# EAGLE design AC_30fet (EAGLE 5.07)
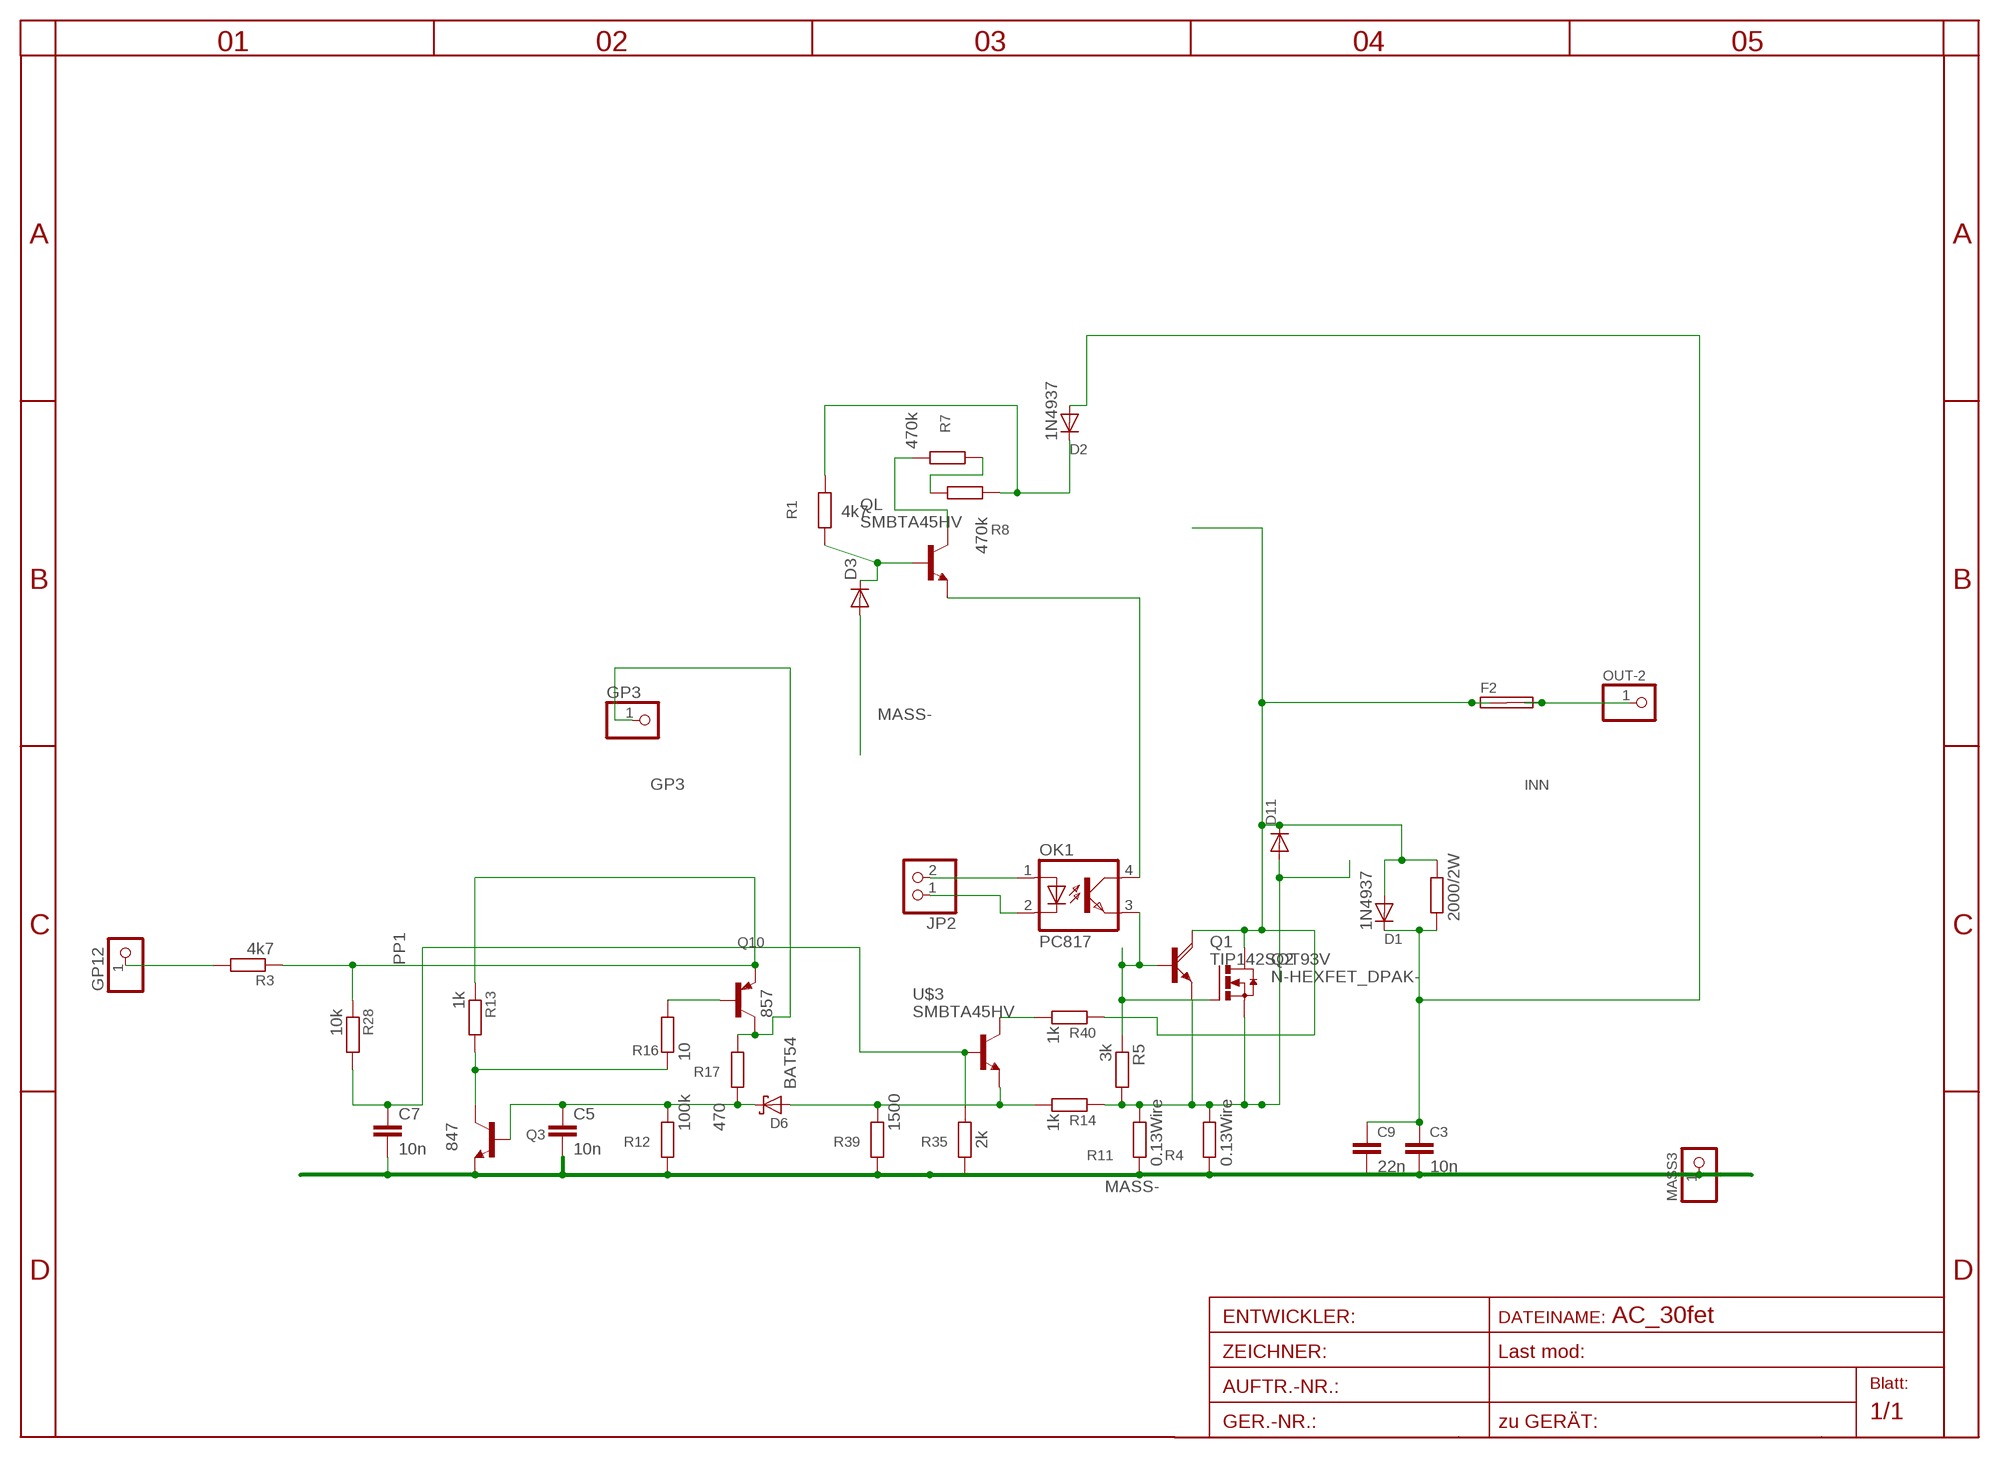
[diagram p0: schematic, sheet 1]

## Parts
C3  10n  C-EU025_050-050X075  [C025_050-050X075]
C5  10n  C-EUC0805  [C0805]
C7  10n  C-EUC0805  [C0805]
C9  22n  C-EU150-054X183  [C150-054X183]
D1  1N4937  1N4004DO41-10  [DO41-10]
D2  1N4937  1N400420  [DO41-20]
D3  DIODE-MINIMELF  [MINIMELF]
D6  BAT54  [SOT23]
D11  DIODE-SMC  [SMC]
F2  SHK20L7MM5  [7MM5]
GP3  PINHD-1X11X0.4  [1X01]
GP12  PINHD-1X11X0.4  [1X01]
JP2  PINHD-1X2STR  [1X02]
MASS3  PINHD-1X13MM2  [1X3MM2]
OK1  PC817  [DIL04]
OUT-2  PINHD-1X13MM2  [1X3MM2]
Q1  TIP142SOT93V  [SOT93V]
Q2  N-HEXFET_DPAK-  [TO252]
Q3  847  BC846ALT1SMD  [SOT23]
Q10  857  BC857ALT1SMD  [SOT23-BEC]
QL  SMBTA45HV  [SOT23HV]
R1  4k7  R-EU_R1206  [R1206]
R3  4k7  R-EU_R0805  [R0805]
R4  0.13Wire  R-EU_0204/5  [0204/5]
R5  3k  R-EU_0207/15  [0207/15]
R7  470k  R-EU_R1206  [R1206]
R8  470k  R-EU_R1206  [R1206]
R11  0.13Wire  R-EU_0204/5  [0204/5]
R12  100k  R-EU_R0805  [R0805]
R13  1k  R-EU_R0805  [R0805]
R14  1k  R-EU_R0805  [R0805]
R16  10  R-EU_R0805  [R0805]
R17  470  R-EU_R0805  [R0805]
R27  2000/2W  R-EU_0207/10  [0207/10]
R28  10k  R-EU_R0805  [R0805]
R35  2k  R-EU_R0805  [R0805]
R39  1500  R-EU_R0805  [R0805]
R40  1k  R-EU_R1206  [R1206]
U$3  SMBTA45HV  [SOT23HV]

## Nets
BQL: D3.C QL.1(B) R1.2
D1: D1.A D11.C F2.1A F2.1B Q1.C Q2.3(D) R27.2 R40.2
DK1: C5.1 D6.3(C) Q3.1(B) R12.1 R17.2
FUSE: GP3.1 Q10.C R17.1
GP3: Q3.3(C) R13.2 R16.1
INN: F2.2A F2.2B OUT-2.1
MASS-: C3.3 C5.2 C7.2 C9.2 D3.A MASS3.1 Q3.2(E) R4.1 R11.1 R12.2 R35.2 R39.2
N$1: R7.1 R8.2
N$2: C3.1 C9.1 D1.C D2.A R27.1
N$3: JP2.1 OK1.2(C)
N$4: OK1.3(EMIT) Q1.B Q2.1(G) R5.1
N$6: D2.C R1.1 R8.1
N$7: JP2.2 OK1.1(A)
N$9: QL.3(C) R7.2
N$11: OK1.4(COL) QL.2(E)
N$12: GP12.1 R3.2
N$14: R40.1 U$3.3(C)
N$16: Q10.B R16.2
N$40: C7.1 R28.2 R35.1 U$3.1(B)
PP1: Q10.E R3.1 R13.1 R28.1
SRC1: D11.A Q1.E Q2.2(S) R4.2 R5.2 R11.2 R14.2
T1E: D6.1(A) R14.1 R39.1 U$3.2(E)

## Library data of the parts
C3 C9 = rcl-2:C-EU: CAPACITOR, European symbol
C5 C7 = rcl:C-EU: CAPACITOR, European symbol
D1 D2 = diode:1N4004: DIODE
D3 D11 = diode:DIODE-: DIODE
D6 = diode:BAT54: Schottky Diodes
F2 = fuse:SHK20L: FUSE HOLDER 5 x 20 mm, SH contact, SHH1 Schukat, E1073 Buerklin
GP3 GP12 MASS3 OUT-2 = pinhead:PINHD-1X1: PIN HEADER
JP2 = pinhead:PINHD-1X2: PIN HEADER
OK1 = optocoupler:PC817: SHARP OPTO COUPLER
Q1 = transistor-power:TIP142: NPN DARLINGTON TRANSISTOR
Q2 = transistor-power:N-HEXFET_?-*: HEXFET® Power MOSFET
Q3 = transistor-npn:BC846*: NPN Transistor
Q10 = transistor-pnp:BC857*: PNP Transistror
QL U$3 = transistor-npn:SMBTA45
R1 R3-R5 R7 R8 R11-R14 R16 R17 R27 R28 R35 R39 R40 = rcl-2:R-EU_: RESISTOR, European symbol

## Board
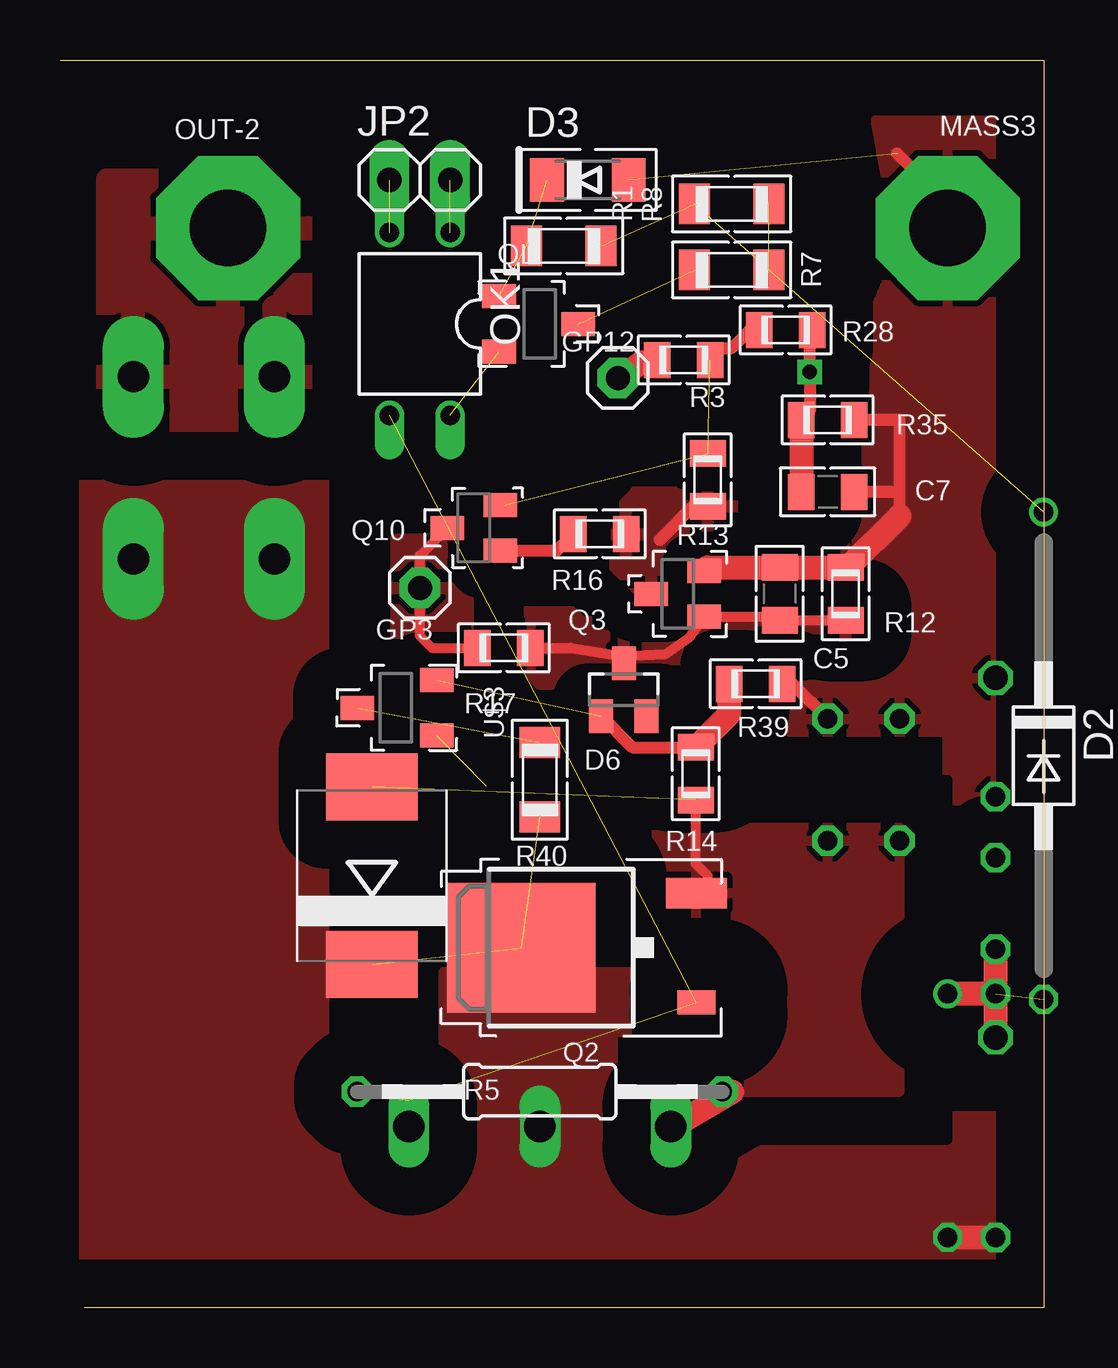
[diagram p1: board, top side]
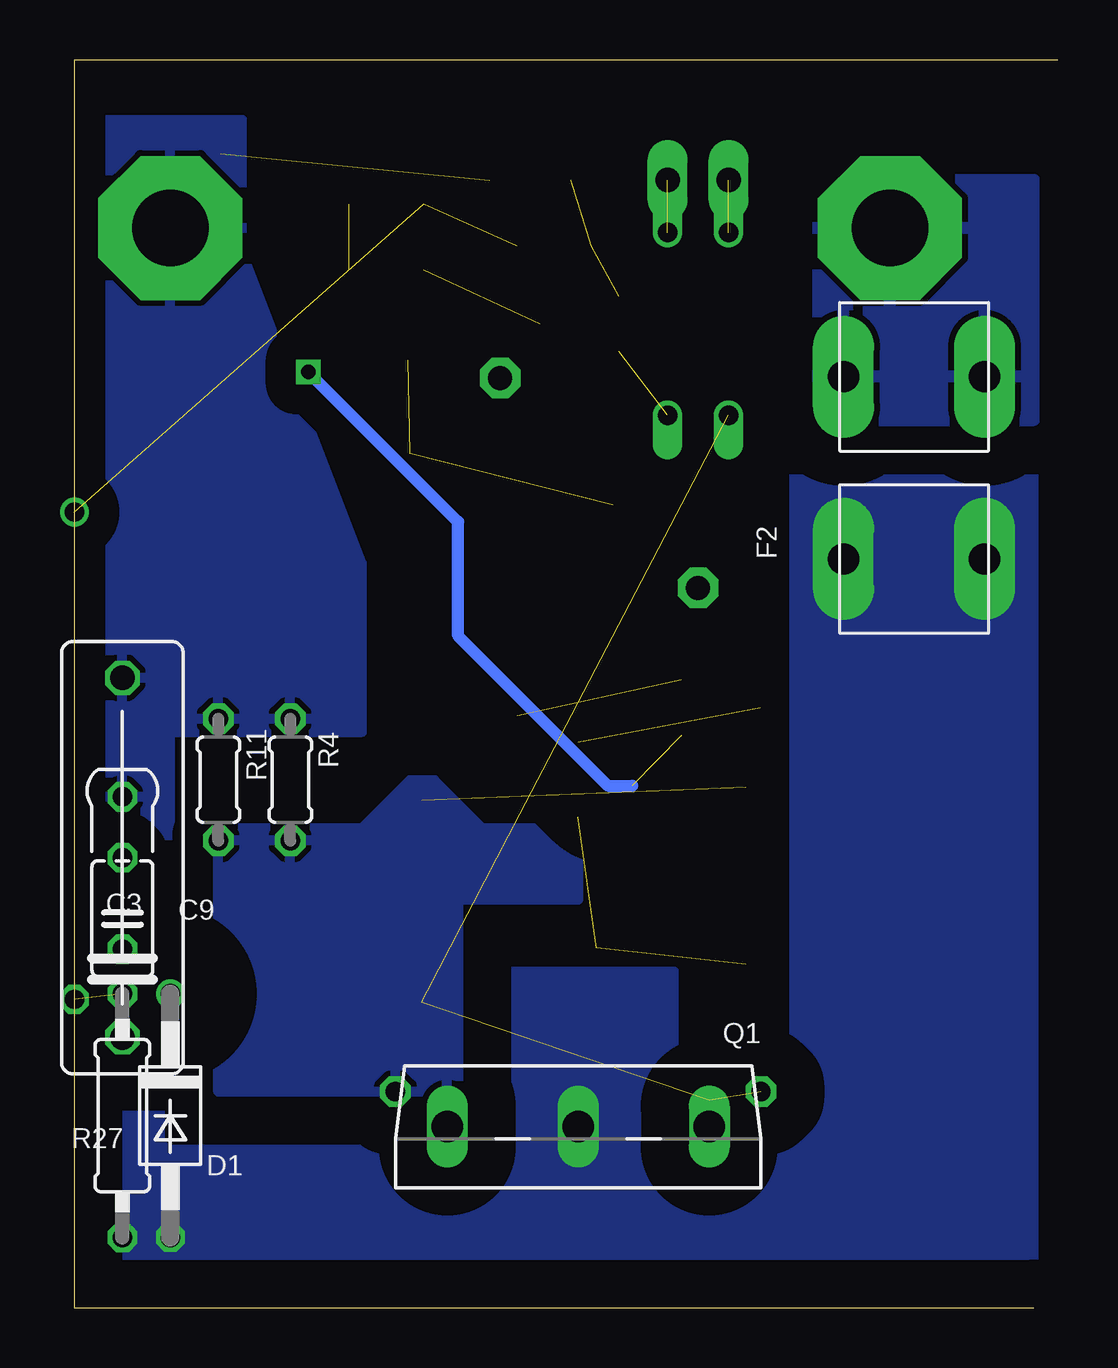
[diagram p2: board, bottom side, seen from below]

Size 41 x 52 mm. Coordinates in mm from the lower left corner, seen from the top.
Outline: 0,52 41,52 41,0 1,0
Copper layers (1*16): Top 0.035mm / dielectric 1.5mm / Bottom 0.035mm
Design rules "default *": minimum track width 12mil, minimum drill 24mil, track to track 8mil, track to pad 8mil, pad to pad 8mil, via to via 8mil, smd to smd 8mil, copper to edge 40mil, drill to drill 8mil, minimum pad ring 8mil, minimum via ring 8mil, stop-mask expansion 4mil, vias tented up to drill 0mil, thermal gap 10mil

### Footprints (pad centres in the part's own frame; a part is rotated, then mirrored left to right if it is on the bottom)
C025_050-050X075 = drill 0.813 octagon: 1 -3.81,0; 2 0,0; 3 2.54,0
C0805 = smd 1.1 x 1.5: 1 -1.1,0; 2 1.1,0
C150-054X183 = drill 1.016 octagon: 1 -7.493,0; 2 7.493,0
DO41-10 = drill 0.8 octagon: A 5.08,0 | drill 0.8 round: C -5.08,0
DO41-20 = drill 0.8 octagon: A 10.16,0 | drill 0.8 round: C -10.16,0
MINIMELF = smd 1.4 x 1.8: A 1.7,0; C -1.7,0
SOT23 = smd 1 x 1.4: 1 -0.95,-1.1; 2 0.95,-1.1; 3 0,1.1
SMC = smd 2.8 x 3.8: A 3.7,0; C -3.7,0
7MM5 = drill 1.3 pad 2.54 long: 1A -3.8,2.94; 1B -3.8,-2.94; 2A 3.8,2.94; 2B 3.8,-2.94
1X01 = drill 1 pad 1.676 octagon: 1 0,0
1X02 = drill 1.016 pad 1.676 long: 1 -1.27,0; 2 1.27,0
1X3MM2 = drill 3.2 pad 6 octagon: 1 0,0
DIL04 = drill 0.813 offset: 1 -1.27,-3.81; 2 1.27,-3.81; 3 1.27,3.81; 4 -1.27,3.81
SOT93V = drill 1.3 pad 1.676 long: B -5.461,-2.54; C 0,-2.54; E 5.461,-2.54
TO252 = smd 1 x 1.6: 1 -2.28,-3.53 | smd 1.27 x 2.54: 2 2.28,-3.53 | smd 5.4 x 6.2: 3 0,3.77
SOT23-BEC = smd 1 x 1.4: B -0.95,-1.1; C 0,1.1; E 0.95,-1.1
SOT23HV = smd 1 x 1.4: 1 -1.15,-1.7; 2 1.15,-1.7; 3 0,1.6
R1206 = smd 1.3 x 1.7: 1 -1.55,0; 2 1.55,0
R0805 = smd 1.1 x 1.5: 1 -1.1,0; 2 1.1,0
0204/5 = drill 0.8 pad 1.27 octagon: 1 -2.54,0; 2 2.54,0
0207/15 = drill 0.8 pad 1.27 octagon: 1 -7.62,0; 2 7.62,0
0207/10 = drill 0.813 octagon: 1 -5.08,0; 2 5.08,0

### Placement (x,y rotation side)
C3  39,18.75 90 bottom
C5  30,29.75 90 top
C7  32,34 0 top
C9  39,18.75 90 bottom
D1  37,8 270 bottom
D2  41,23 270 top
D3  22,47 0 top
D6  23.5,25.75 0 top
D11  13,18 90 top
F2  6,35 90 bottom
GP3  15,30 0 top
GP12  23.25,38.75 0 top
JP2  15,47 0 top
MASS3  37,45 0 top
OK1  15,41 180 top
OUT-2  7,45 180 top
Q1  20,5 180 bottom
Q2  23,15 90 top
Q3  25.75,29.75 90 top
Q10  17.25,32.5 90 top
QL  20,41 270 top
R1  21,44.25 180 top
R3  26,39.5 180 top
R4  32,22 270 bottom
R5  20,9 0 top
R7  28,43.25 180 top
R8  28,46 0 top
R11  35,22 270 bottom
R12  32.75,29.75 90 top
R13  27,34.5 270 top
R14  26.5,22.25 270 top
R16  22.5,32.25 180 top
R17  18.5,27.5 0 top
R27  39,8 270 bottom
R28  30.25,40.75 0 top
R35  32,37 0 top
R39  29,26 0 top
R40  20,22 270 top
U$3  14,25 90 top

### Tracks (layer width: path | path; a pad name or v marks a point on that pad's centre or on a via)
BQL  (2 unrouted)
D1  (2 unrouted)
  Top 1: D1.A R27.2
  pour Top (isolate 2, rank 2, no thermals): 1,0 1,35 11,35 11,11 16,11 16,14 24,14 24,8 40,8 41,7 41,0
  pour Bottom (isolate 2, rank 2, no thermals): 1,0 1,35 11,35 11,11 16,11 16,14 24,14 24,8 40,8 41,7 41,0
DK1
  Top 0.406: 23.4,27.15 D6.3 | 23.4,27.15 25.25,27.25 26.25,27.95 Q3.1 29.6,28.8 C5.1 R12.1 | R17.2 21.3,27.5 23.4,27.15
  pour Top (isolate 1.5, rank 4): 33,30 33,28 28,28 26,26 20,26 19,27 19,29 26,29 27,30
FUSE
  Top 0.406: R17.1 15.5,27.5 15,28 15,31.35 Q10.C
  pour Top (isolate 1.5): 17,32 14,32 14,27 17,27
GP3
  Top 0.5: R13.2 26.4,33.4 25,32
  pour Top (isolate 1, rank 3): 23,33 24,34 28,34 28,32 27,31 26,31 25,30 24,30 23,31
INN
  pour Top: 10,37 2,37 2,47 10,47
  pour Bottom: 10,37 1,37 1,47 10,47
MASS-  (1 unrouted)
  Top 0.5: 34.9,48.1 37,46 MASS3.1 | R39.2 30.54,26 R4.1 | Q3.2 27,30.85 | R35.2 35,37 35,34 | 35,34 C7.2 | R12.2 32.85,30.85 | 35,33 35,34
  Top 1: R12.2 C5.2 27,30.85 | 32.85,30.85 35,33
  pour Top (isolate 2, rank 2): 34,49.5 40,49.5 40,17 37,17 37,24 29,24 29,28 32,29 32,37 35,44
  pour Bottom (isolate 1.27, rank 2): 34,49.5 40,49.5 40,17 37,17 37,24 29,24 29,31 34,44
N$1  (1 unrouted)
N$2  (1 unrouted)
  Top 1: D1.C R27.1 C9.1 C3.1
N$3  (1 unrouted)
N$4  (3 unrouted)
  Top 1: Q1.B 14.54,8.63
N$6  (2 unrouted)
N$7  (1 unrouted)
N$9  (1 unrouted)
N$11  (1 unrouted)
N$12
  Top 1: GP12.1 24.25,39.4 R3.2
N$14  (1 unrouted)
N$16
  Top 0.5: Q10.B 20.7,31.55 R16.2
N$40  (via drill 0.6)  (1 unrouted)
  Top 0.5: R35.1 31.25,37.35 v31.25,39 31.25,40.65 R28.2
  Top 1: R35.1 C7.1
  Bottom 0.5: 17.75,21.75 18.75,21.75 25,28 25,32.75 v31.25,39
PP1  (2 unrouted)
  Top 0.406: Q10.E 18.55,33.45
  Top 0.5: R28.1 28.75,40.75 28,40 27.6,40 R3.1
SRC1  (1 unrouted)
  Top 0.406: R14.2 26.5,18.5 27,18
  Top 1.016: Q1.E 25.54,7.54 28,9
  pour Top (isolate 3): 25,9 35,9 35,20 29,20 27,22 26,22 24,20 20,20 20,17 25,17
  pour Bottom (isolate 3): 25,9 35,9 35,20 29,20 27,22 26,22 24,20 20,20 20,17 25,17
T1E  (1 unrouted)
  Top 0.5: R14.1 23.85,23.35 D6.1
  Top 1: R39.1 27.9,24.75 R14.1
